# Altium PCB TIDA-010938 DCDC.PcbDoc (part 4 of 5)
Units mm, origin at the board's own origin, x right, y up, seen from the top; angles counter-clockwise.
Board outline 275 x 165 mm, 4 copper layers (Top Layer, Layer 1, Layer 2, Bottom Layer), stack 1.787 mm thick; 436 components, 216 nets, 1367 pads, 1992 vias.
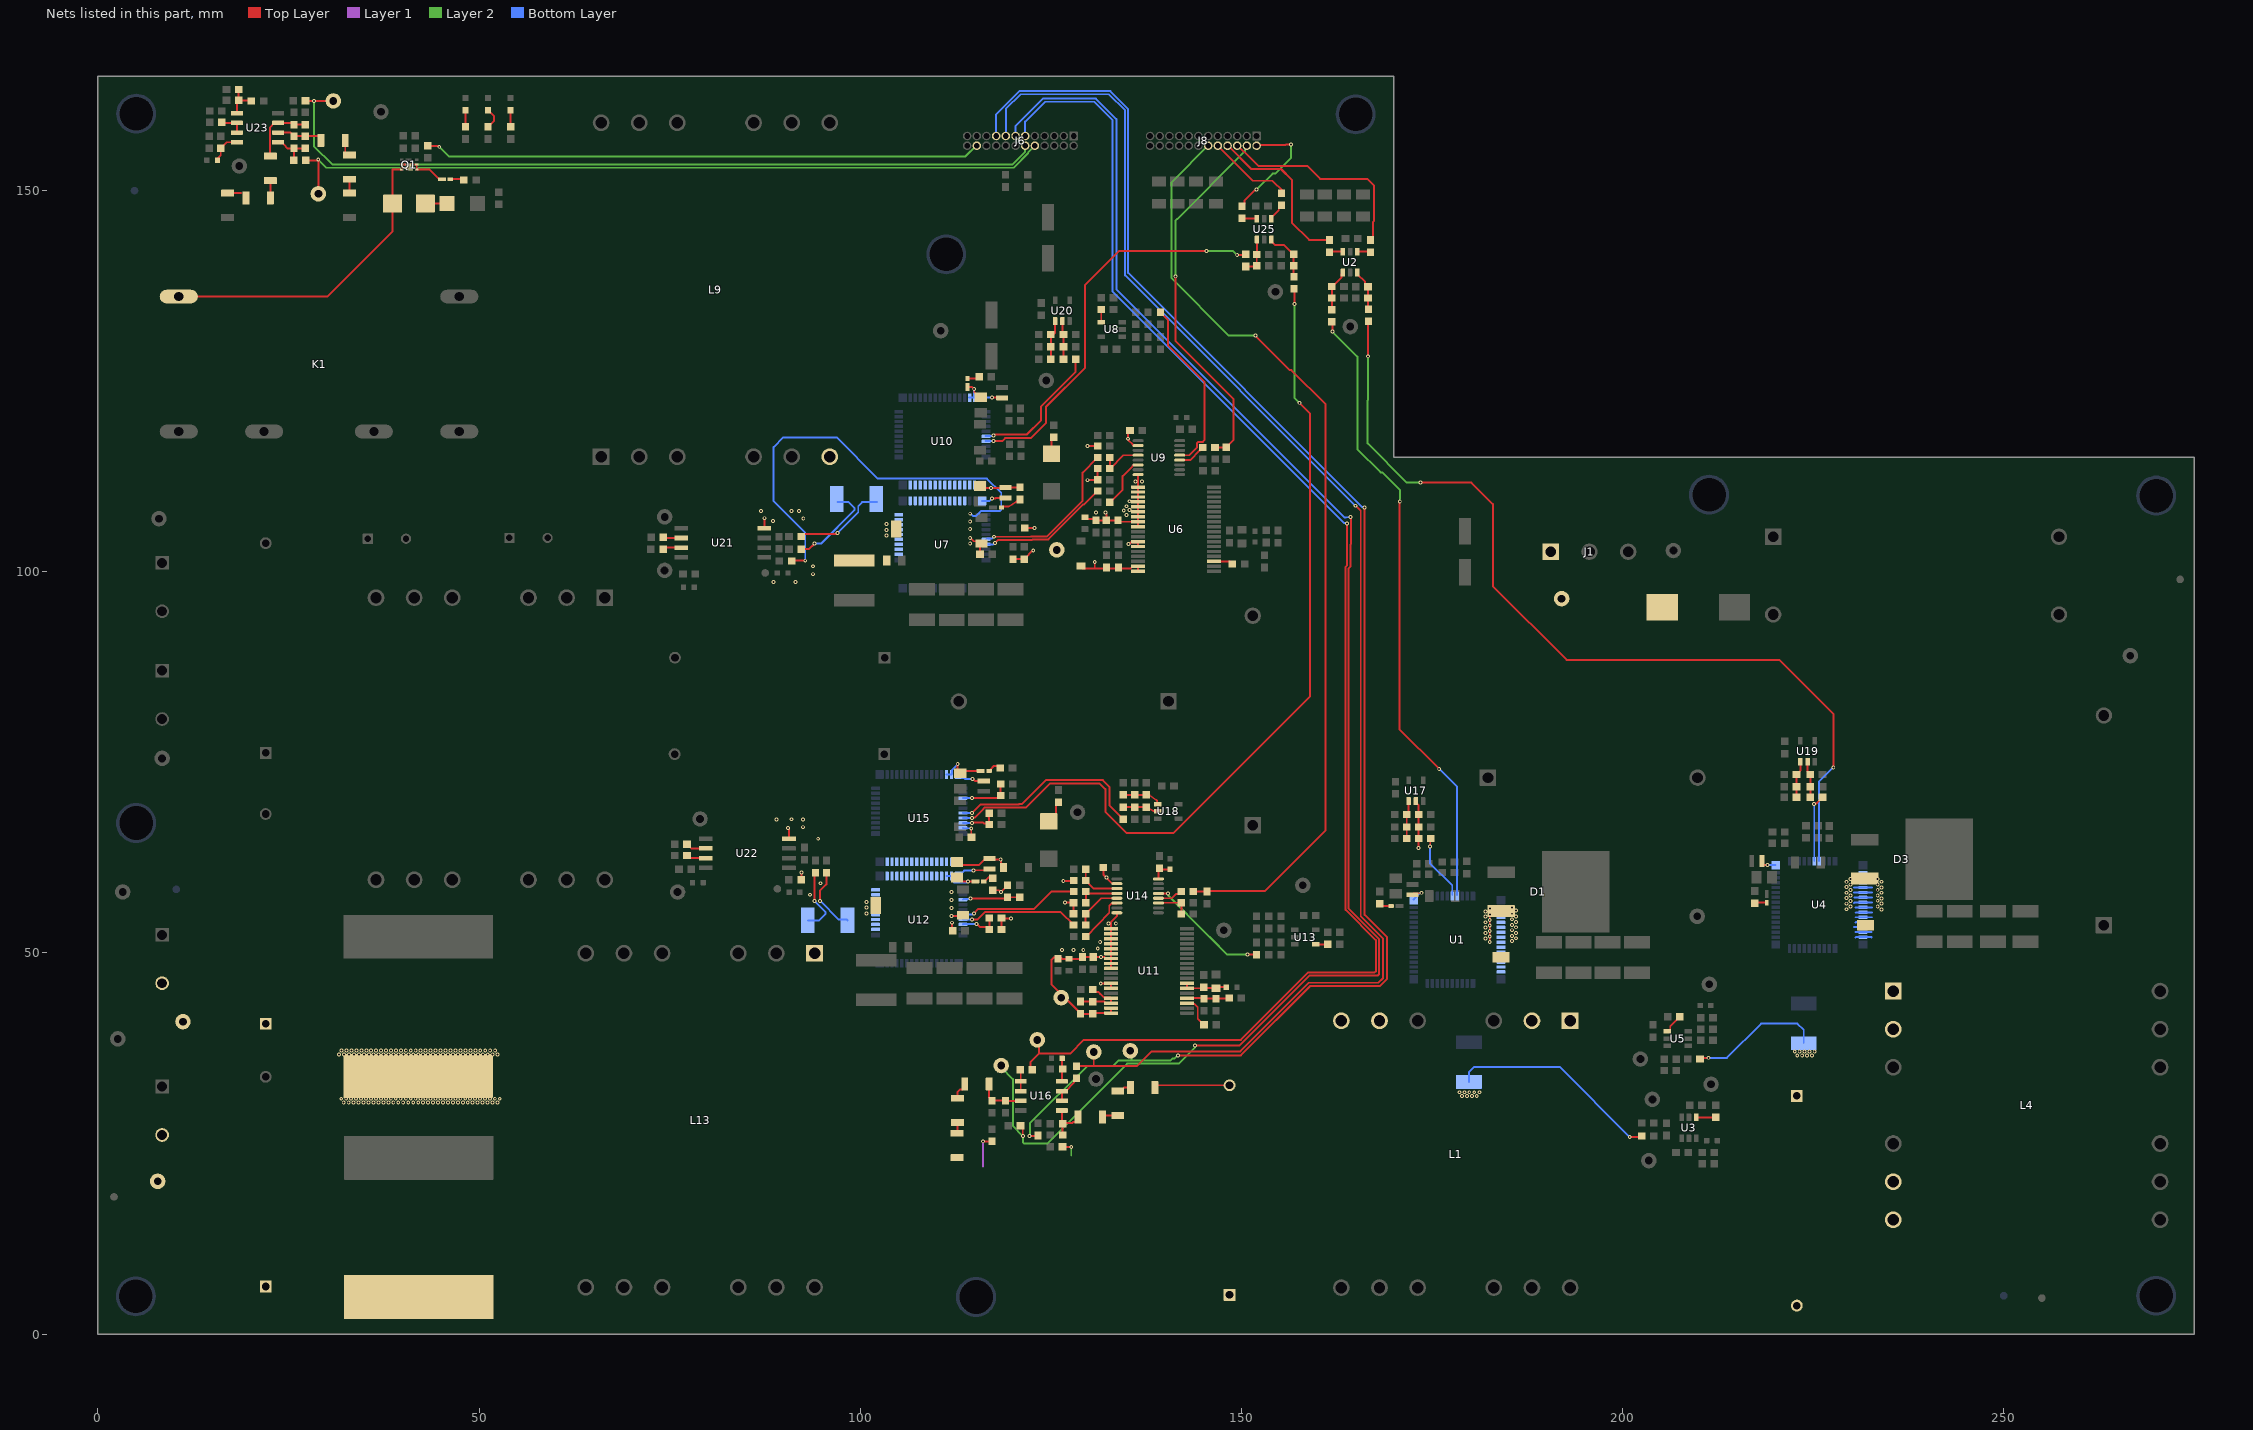
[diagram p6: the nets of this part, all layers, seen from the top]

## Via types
v1: diameter 0.508, hole 0.254, Top Layer to Bottom Layer, tented both sides, 1977 vias
v2: diameter 0.508, hole 0.254, Top Layer to Bottom Layer, 15 vias

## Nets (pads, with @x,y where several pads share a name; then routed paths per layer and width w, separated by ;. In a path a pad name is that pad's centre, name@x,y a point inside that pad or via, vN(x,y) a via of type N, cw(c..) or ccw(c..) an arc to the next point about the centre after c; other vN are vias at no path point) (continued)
NetC65_1: C65.1 D20.1 U10.40 U10.41 | length 4.3
  Top Layer w0.254: D20.1@114.052,124.232 114.678,124.232 114.948,123.962 114.948,123.575 115.632,122.891 C65.1@115.797,122.891
  Bottom Layer w0.254: U10.40@114.274,122.856 114.924,122.856 114.936,122.867 114.936,123.952 v1(114.947,123.964)
NetC66_1: C66.1 R98.1
NetC67_2: C67.2 R75.2 R79.2 U17.1 | length 5
  Top Layer w0.254: R75.2@171.69,65.009 R79.2@171.69,66.509 C67.2@171.69,68.155 171.935,68.4 U17.1@171.935,69.928
NetC69_2: C69.2 R49.2 U12.45 | length 7.2
  Top Layer w0.254: v1(114.462,57.164) 119.185,57.164 C69.2@119.327,57.306 120.556,57.306 R49.2@120.564,57.315
  Bottom Layer w0.254: U12.45@113.462,56.989 113.56,57.087 114.316,57.087 114.394,57.164 v1(114.462,57.164)
NetC73_2: C73.2 C77.1 FB6.2 U11.6 U11.7 | length 6
  Top Layer w0.254: U11.7@142.862,46.02 U11.6@142.862,45.37 144.922,45.37 C77.1@145.062,45.51 145.195,45.377 C73.2@146.672,45.377 146.805,45.51 FB6.2@148.012,45.51
NetC76_1: C76.1 R48.2 R54.1 U11.33 U11.34 | length 7.6
  Top Layer w0.254: R54.1@128.899,43.633 130.474,43.633 C76.1@130.499,43.608 132.023,43.608 132.212,43.42 U11.34@132.912,43.42 U11.33@132.912,44.07 132.814,44.168 131.951,44.168 131.474,44.645 131.22,44.899 130.809,44.899 R48.2@130.512,45.197
NetC78_2: C78.2 R76.2 R80.2 U18.1 | length 5.1
  Top Layer w0.254: R76.2@134.508,70.744 R80.2@136.008,70.744 C78.2@137.508,70.744 137.856,70.701 137.937,70.701 138.85,70.052 138.922,69.98 138.968,69.707 138.968,69.686 U18.1@139.001,69.513
NetC79_2: C79.2 R57.2 U12.50 | length 5.3
  Top Layer w0.254: v1(115.241,53.81) 115.31,53.81 115.687,53.432 116.582,53.432 C79.2@116.93,53.084 R57.2@116.93,54.582
  Bottom Layer w0.254: U12.50@113.462,53.739 113.498,53.774 115.205,53.774 v1(115.241,53.81)
NetC80_1: C80.1 D21.1 U12.40 U12.41 | length 6.1
  Top Layer w0.254: C80.1@112.689,59.897 113.197,59.389 v2@114.11,59.389 ; D21.1@114.964,59.379 v2(114.134,59.379) ; v2@114.11,59.389 114.134,59.412 v2(114.134,59.379) ; v2@114.11,59.389 114.1,59.379 v2(114.134,59.379) ; v2@114.11,59.389 114.124,59.389 v2(114.134,59.379)
  Bottom Layer w0.254: U12.40@111.312,60.099 U12.41@111.962,60.099 112.06,60.001 112.06,59.488 112.302,59.247 113.933,59.247 114.065,59.379 v2(114.134,59.379)
NetC81_2: C81.2 R50.2 R52.2 U11.4 | length 5.6
  Top Layer w0.254: U11.4@142.862,44.07 145.025,44.07 C81.2@145.087,44.007 R52.2@146.672,44.007 148.312,44.007 R50.2@148.387,44.082
NetC82_2: C82.2 R77.2 R81.2 U17.2 | length 6.3
  Top Layer w0.254: U17.2@172.885,69.928 172.885,69.728 173.252,69.361 C82.2@173.252,68.155 R81.2@173.252,66.509 R77.2@173.252,65.009 173.252,63.777 v1@173.241,63.766
  other v1: 173.207,63.766
NetC83_2: C83.2 R78.2 R82.2 U18.2 | length 4.6
  Top Layer w0.254: R78.2@134.508,69.119 R82.2@136.008,69.119 C83.2@137.508,69.119 137.856,68.915 C83.2@137.895,68.915 ; C83.2@137.553,69.119 U18.2@138.583,68.554
NetC84_1: C84.1 FB10.2 U14.16 | length 2.9
  Top Layer w0.254: U14.16@139.116,59.718 139.116,60.995 C84.1@139.246,61.125 139.396,60.975 FB10.2@140.639,60.975
NetC86_2: C86.2 R83.2 R90.2 U19.1 | length 4.9
  Top Layer w0.254: R83.2@222.807,70.424 R90.2@222.807,71.804 C86.2@222.807,73.424 222.832,73.424 223.18,73.772 223.18,73.797 223.312,73.929 U19.1@223.312,75.073
NetC87_2: C87.2 R84.2 R91.2 U20.1 | length 5
  Top Layer w0.254: R84.2@125,127.786 125,129.286 125,130.842 125.025,130.842 125.558,131.375 U20.1@125.558,132.578
NetC88_2: C88.2 R158.1 U14.5 | length 6.4
  Top Layer w0.254: R158.1@129.575,53.673 129.571,53.677 C88.2@129.571,55.147 131.602,57.178 U14.5@133.666,57.178
NetC89_2: C89.2 R59.1 U14.3 | length 6
  Top Layer w0.254: R59.1@129.579,60.99 C89.2@129.579,59.498 130.629,58.448 U14.3@133.666,58.448
NetC90_2: C90.2 R35.1 U9.4 | length 5.9
  Top Layer w0.254: R35.1@132.736,114.981 C90.2@132.736,113.541 132.761,113.541 134.512,115.292 U9.4@136.452,115.292
NetC91_2: C91.2 R85.2 R92.2 U19.2 | length 4.8
  Top Layer w0.254: U19.2@224.262,75.073 224.262,73.772 224.61,73.424 C91.2@224.629,73.424 R92.2@224.629,71.804 R85.2@224.629,70.424
NetC92_2: C92.2 R62.2 U14.11 | length 4.4
  Top Layer w0.254: U14.11@139.116,56.543 139.144,56.571 139.773,56.571 139.788,56.586 C92.2@142.013,56.586 ; R62.2@142.149,55.058 C92.2@142.149,56.525
NetC95_2: C95.2 U15.51 | length 2.3
  Top Layer w0.254: v1(114.556,66.313) 114.556,65.521 114.669,65.408 C95.2@114.669,65.173
  Bottom Layer w0.254: U15.51@113.462,66.406 113.509,66.359 114.509,66.359 v1(114.556,66.313)
NetC96_2: C96.2 R65.2 U15.45 | length 6.6
  Top Layer w0.254: v1(114.669,70.306) 116.412,70.306 116.42,70.313 118.07,70.313 R65.2@118.418,70.661 C96.2@118.418,72.163
  Bottom Layer w0.254: U15.45@113.462,70.306 v1(114.669,70.306)
NetC97_2: C97.2 R89.2 R93.2 U20.2 | length 4.9
  Top Layer w0.254: U20.2@126.508,132.578 126.508,130.992 126.658,130.842 126.658,129.286 R89.2@126.658,127.786
NetC98_2: C98.2 R70.2 U15.50 | length 5.3
  Top Layer w0.254: v1(114.669,67.047) 114.718,67.096 116.095,67.096 116.198,66.993 116.786,66.993 C98.2@116.93,66.849 ; C98.2@116.663,66.533 116.862,66.732 116.862,67.825 R70.2@116.663,68.025
  Bottom Layer w0.254: U15.50@113.462,67.056 113.467,67.051 114.665,67.051 v1(114.669,67.047)
NetC99_1: C99.1 D22.1 U15.40 U15.41 | length 6.5
  Top Layer w0.254: v1(112.781,74.786) 112.781,73.897 C99.1@113.121,73.556 113.45,73.885 D22.1@115.712,73.885
  Bottom Layer w0.254: U15.40@111.312,73.416 U15.41@111.962,73.416 112.06,73.514 112.06,74.026 112.781,74.747 v1(112.781,74.786)
NetC102_2: C102.2 FB3.2 U16.8 | length 3.1
  Top Layer w0.254: U16.8@126.451,33.145 126.451,34.68 C102.2@126.541,34.77 126.475,34.836 FB3.2@126.475,36.175
NetC103_2: C103.2 R42.2 R106.1 U16.5 | length 5.8
  Top Layer w0.254: U16.5@126.451,29.335 126.451,27.69 126.541,27.69 127.79,27.69 127.924,27.824 128.252,27.824 128.575,28.147 R42.2@128.575,28.475 ; R106.1@126.541,26.125 C103.2@126.541,27.6
NetC104_2: C104.2 R53.2 R139.1 U23.3 | length 9.1
  Top Layer w0.254: R53.2@21.966,154.608 22.253,154.608 22.576,154.931 22.576,158.308 23.153,158.885 U23.3@23.628,158.885 25.481,158.885 C104.2@25.708,158.658 R139.1@27.206,158.658
NetC105_2: C105.2 R31.2 R140.2 U16.3 | length 6.1
  Top Layer w0.254: R31.2@116.91,32.805 116.91,31.029 117.294,30.645 R140.2@117.294,30.62 C105.2@119.052,30.62 119.067,30.605 U16.3@121.051,30.605
NetC109_1: C109.1 R74.2 R141.1 U23.2 | length 6.2
  Top Layer w0.254: U23.2@23.628,157.615 25.263,157.615 25.708,157.17 C109.1@25.708,157.145 R141.1@27.206,157.145 28.918,157.145 29.241,156.822 R74.2@29.241,156.582
NetC109_2: C109.2 R141.2 R152.1 U23.1 | length 5.5
  Top Layer w0.254: U23.1@23.628,156.345 24.103,156.345 24.635,155.813 24.635,155.762 24.852,155.545 C109.2@25.708,155.545 ; R152.1@25.681,153.977 25.708,154.004 C109.2@25.708,155.545 ; R141.2@27.206,155.545 C109.2@25.708,155.545
NetC116_2: C116.2 R109.2 R131.2 U2.1 | length 5.5
  Top Layer w0.254: R109.2@161.859,134.38 R131.2@161.859,135.914 C116.2@161.859,137.417 161.884,137.417 163.128,138.661 163.128,139.085 U2.1@163.301,139.258
NetC118_2: C118.2 R112.2 R129.2 U2.3 | length 5.4
  Top Layer w0.254: U2.3@165.201,139.258 165.201,139.058 166.236,138.023 166.236,137.731 166.584,137.383 C118.2@166.601,137.383 R129.2@166.601,135.919 166.601,134.512 R112.2@166.665,134.448
NetC120_2: C120.2 R117.2 R127.2 U25.1 | length 4.9
  Top Layer w0.254: R117.2@150.557,140.05 151.898,140.05 R127.2@152.005,140.158 C120.2@152.005,141.619 152.042,141.656 U25.1@152.042,143.538
NetC122_2: C122.2 R120.2 R125.2 U25.3 | length 6.8
  Top Layer w0.254: U25.3@153.93,143.586 153.93,143.386 154.455,142.861 155.608,142.861 156.819,141.65 C122.2@156.844,141.65 R125.2@156.844,140.158 156.844,138.785 R120.2@156.908,138.722
NetC151_2: C151.2 R60.1 U14.4 | length 5.6
  Top Layer w0.254: C151.2@129.571,56.6 129.582,56.612 R60.1@129.582,58.054 129.823,57.813 U14.4@133.666,57.813
NetC153_2: C153.2 R12.2 R41.1 U23.5 | length 4.9
  Top Layer w0.254: U23.5@18.228,160.155 18.228,161.62 R41.1@18.458,161.85 ; R12.2@18.458,163.25 R41.1@18.458,161.85 ; C153.2@20.128,161.775 20.053,161.85 R41.1@18.458,161.85
NetC155_2: C155.2 FB11.2 U23.8 | length 3.9
  Top Layer w0.254: FB11.2@15.686,154.25 16.108,154.672 C155.2@16.108,155.545 16.108,155.57 16.883,156.345 U23.8@18.228,156.345
NetD1_2: D1.2 L1.1 L1.2 TP12.1 U1.2 U1.3 U1.4 U1.5 U1.6 U1.7 U1.8 U1.9 U1.10 U1.11 U1.12 U1.13 U1.14 U1.15 | length 4.4
  Top Layer w0.254: v1(182.577,51.461) 182.577,55.061 182.6,55.083 v1(182.6,55.821)
  other v1: 185.487,51.547 182.035,51.902 186.009,51.93 182.577,52.154 185.487,52.239 182.035,52.595 186.009,52.623 182.577,52.898 185.487,52.984 182.035,53.34 186.009,53.367 182.577,53.591 185.487,53.676 182.035,54.032 186.009,54.06 182.577,54.335 185.487,54.421 182.035,54.777 186.009,54.805 182.6,55.061 185.495,55.145 182.035,55.425 186.009,55.574 185.495,55.99
NetD3_2: D3.2 L4.1 L4.2 TP16.1 U4.2 U4.3 U4.4 U4.5 U4.6 U4.7 U4.8 U4.9 U4.10 U4.11 U4.12 U4.13 U4.14 U4.15 | length 24.5
  Bottom Layer w0.254: 230.375,53.385 U4.13@231.532,53.385 232.603,53.385 ; 230.375,56.573 230.438,56.635 U4.8@231.532,56.635 232.739,56.635 232.744,56.64 ; 230.375,57.935 U4.6@231.532,57.935 232.744,57.935 ; 230.375,58.585 U4.5@231.532,58.585 232.744,58.585 ; 230.438,57.284 230.439,57.285 U4.7@231.532,57.285 232.719,57.285 232.744,57.311 ; 230.562,52.049 230.598,52.085 U4.15@231.532,52.085 232.628,52.085 232.665,52.049 ; 230.562,52.735 U4.14@231.532,52.735 232.665,52.735 ; 230.562,53.973 230.624,54.035 U4.12@231.532,54.035 232.599,54.035 232.665,54.101 ; 230.562,54.685 U4.11@231.532,54.685 232.719,54.685 ; 230.562,55.273 230.624,55.335 U4.10@231.532,55.335 232.692,55.335 ; 230.562,55.985 U4.9@231.532,55.985 232.692,55.985
  other v1: 233.972,55.721 229.382,55.735 229.901,56.078 233.462,56.106 229.382,56.46 233.972,56.465 229.901,56.822 233.462,56.85 233.972,57.158 229.382,57.204 229.901,57.515 233.462,57.543 229.382,57.897 233.972,57.902 229.901,58.26 233.462,58.287 233.972,58.595 229.382,58.641 229.901,58.952 233.462,58.98 229.382,59.334 233.972,59.339 229.901,59.697 233.462,59.724
NetD5_2: D5.2 R21.2 | length 3.6
  Top Layer w0.254: D5.2@124.148,116.402 D5.2@125.075,115.475 125.075,117.342 R21.2@125.37,117.637
NetD8_2: D8.2 R46.2 | length 3.1
  Top Layer w0.254: D8.2@123.731,67.004 D8.2@123.781,67.004 ; D8.2@124.721,67.261 125.661,68.2 125.661,69.431 R46.2@126.009,69.779
NetD11_2: D11.2 D12.2 | length 2.8
  Top Layer w0.254: D11.2@42.944,148.312 D12.2@45.794,148.312
NetD13_1: D13.1 R147.2 | length 2
  Top Layer w0.254: R147.2@48.211,158.424 D13.1@48.211,160.406
NetD14_2: D14.2 R7.2 | length 1.7
  Top Layer w0.254: D14.2@46.375,151.5 47.916,151.5 R7.2@48.007,151.41
NetD15_1: D15.1 R153.2 | length 2.8
  Top Layer w0.254: R153.2@51.177,158.375 51.977,159.175 51.977,159.742 D15.1@51.177,160.542
NetD16_1: D16.1 R154.2 | length 2.1
  Top Layer w0.254: R154.2@54.142,158.432 D16.1@54.142,160.542
NetD17_2: D17.2 R105.2 | length 1.6
  Top Layer w0.254: R105.2@168.131,56.456 168.428,56.159 D17.2@169.631,56.159
NetD18_2: D18.2 R132.2 | length 1.6
  Top Layer w0.254: R132.2@217.328,56.52 217.448,56.64 D18.2@218.902,56.64
NetD19_2: D19.2 R133.2 | length 2.8
  Top Layer w0.254: D19.2@118.524,108.426 118.647,108.549 119.454,108.549 ; 119.455,108.55 120.587,109.26 120.605,109.26 R133.2@120.953,109.49
NetD20_2: D20.2 R135.2 | length 1.6
  Top Layer w0.254: D20.2@114.052,125.347 115.345,125.347 R135.2@115.595,125.597
NetD21_2: D21.2 R136.2 | length 1.4
  Top Layer w0.254: D21.2@116.204,59.379 116.304,59.379 116.893,59.968 117.297,59.968 R136.2@117.297,59.898
NetD22_2: D22.2 R138.2 | length 1.9
  Top Layer w0.254: D22.2@116.899,73.885 116.999,73.885 117.122,74.008 117.122,74.108 117.541,74.526 118.097,74.526 R138.2@118.369,74.255
NetJ1_1: J1.1 L3.2 TP40.1
NetL2_2: L2.2 U1.42 | length 2.7
  Top Layer w0.254: L2.2@172.425,57.634 172.623,57.832 173.497,57.832 173.556,57.892 v1(173.625,57.892)
  Bottom Layer w0.254: U1.42@172.591,57.042 172.616,57.042 173.417,57.843 173.576,57.843 v1(173.625,57.892)
NetL5_2: L5.2 U4.42 | length 2.2
  Top Layer w0.254: L5.2@218.291,62.067 218.291,61.734 218.489,61.536 v1(219.026,61.536)
  Bottom Layer w0.254: v1@219.026,61.51 U4.42@220.082,61.51
NetL7_2: L7.2 U7.42 | length 3.3
  Top Layer w0.254: v2(117.262,109.611) 117.706,109.611 117.803,109.708 L7.2@119.048,109.708
  Bottom Layer w0.254: U7.42@115.983,109.304 116.987,109.304 117.262,109.58 v2(117.262,109.611)
NetL9_6: L9.6 R58.1 R134.1 | length 12
  Top Layer w0.254: R58.1@92.249,102.944 92.273,102.967 93.255,102.967 v1(94,103.712)
  Bottom Layer w0.254: v1(94,103.712) 94.863,103.712 99.231,108.081 99.231,108.376 98.474,109.133 R134.1@96.989,109.133
NetL10_2: L10.2 U10.42 | length 2.7
  Top Layer w0.254: v1(117.259,122.867) 117.28,122.846 118.59,122.846 L10.2@118.611,122.826
  Bottom Layer w0.254: U10.42@115.899,122.856 117.247,122.856 v1(117.259,122.867)
NetL11_2: L11.2 U12.42 | length 4.4
  Top Layer w0.254: v2(114.843,60.798) 114.892,60.846 116.774,60.846 L11.2@116.968,61.04
  Bottom Layer w0.254: U12.42@112.937,60.099 112.937,60.124 113.611,60.798 v2(114.843,60.798)
NetL13_1: L13.1 R96.1 R137.1 | length 8.5
  Top Layer w0.254: v1(94,56.813) R96.1@94,60.403
  Bottom Layer w0.254: R137.1@93.125,54.286 94.599,54.286 95.457,55.145 95.457,55.356 v1(94,56.813)
NetL14_2: L14.2 U15.42 | length 3.6
  Top Layer w0.254: v1(114.734,72.822) 114.761,72.822 115.017,72.565 L14.2@116.198,72.565
  Bottom Layer w0.254: U15.42@112.937,73.416 112.937,73.391 113.36,72.968 113.575,72.968 113.721,72.822 v1(114.734,72.822)
NetR4_1: R4.1 U8.4 | length 1.7
  Top Layer w0.254: R4.1@131.611,134.417 131.614,134.413 U8.4@131.614,132.735
NetR8_1: R8.1 U3.1 | length 2.6
  Top Layer w0.254: U3.1@209.657,28.434 212.2,28.434 R8.1@212.207,28.44
NetR14_1: R14.1 U13.4 | length 1.6
  Top Layer w0.254: U13.4@159.73,51.128 R14.1@161.328,51.128
NetR19_1: R19.1 U5.1 | length 2.7
  Top Layer w0.254: U5.1@205.881,39.716 206.081,39.716 206.254,39.889 206.254,40.376 207.127,41.25 207.127,41.275 207.475,41.623 R19.1@207.5,41.623
NetR22_2: R22.2 U6.3 | length 2.6
  Top Layer w0.254: U6.3@146.395,101.367 147.815,101.367 147.821,101.361 148.468,101.361 R22.2@148.816,101.013
NetR26_1: R26.1 U23.6 U23.7 | length 3.3
  Top Layer w0.254: R26.1@16.261,158.983 16.36,158.885 U23.6@18.228,158.885 U23.7@18.228,157.615
NetR28_2: R28.2 R30.1 | length 1.4
  Top Layer w0.254: R28.2@112.693,26.348 112.729,26.384 112.729,27.714 R30.1@112.766,27.75
NetR30_2: R30.2 R31.1 | length 2.4
  Top Layer w0.254: R30.2@112.766,30.95 112.766,31.781 113.067,32.082 113.387,32.082 113.71,32.405 R31.1@113.71,32.805
NetR33_2: R33.2 R36.1 | length 1.9
  Top Layer w0.254: R36.1@133.775,31.895 134.175,31.895 134.621,32.341 R33.2@135.447,32.341
NetR36_2: R36.2 R42.1 | length 2.1
  Top Layer w0.254: R42.1@131.775,28.475 131.995,28.695 R36.2@133.775,28.695
NetR38_1: R38.1 U9.6 | length 6.8
  Top Layer w0.254: R38.1@132.736,109.118 132.761,109.118 134.419,110.776 134.419,112.554 135.73,113.864 135.888,114.022 U9.6@136.452,114.022
NetR43_2: R43.2 R44.1 | length 1.8
  Top Layer w0.254: R43.2@17.011,149.675 18.778,149.675
NetR44_2: R44.2 R53.1 | length 1.9
  Top Layer w0.254: R53.1@22.469,151.472 R53.1@22.617,151.323 22.629,151.311 R44.2@22.629,149.589
NetR47_2: R47.2 U11.3 | length 4.3
  Top Layer w0.254: U11.3@142.862,43.42 142.96,43.322 143.822,43.322 144.268,42.876 144.268,41.363 145.062,40.569 R47.2@145.087,40.569
NetR51_2: R51.2 U9.12 | length 3.7
  Top Layer w0.254: U9.12@141.902,114.657 143.296,114.657 144.561,115.923 144.561,115.948 144.909,116.296 R51.2@144.934,116.296
NetR61_2: R61.2 U21.6 | length 2.4
  Top Layer w0.254: R61.2@74.139,104.52 74.225,104.434 U21.6@76.52,104.434
NetR63_1: R63.1 U14.6 | length 6.4
  Top Layer w0.254: R63.1@129.667,52.144 132.664,55.282 132.664,56.172 133.007,56.515 133.638,56.515 U14.6@133.666,56.543
NetR66_2: R66.2 U21.7 | length 2.5
  Top Layer w0.254: R66.2@74.139,102.964 74.339,103.164 U21.7@76.52,103.164
NetR68_2: R68.2 R69.1 | length 1.8
  Top Layer w0.254: R68.2@33,149.675 R69.1@33,151.491
NetR69_2: R69.2 R74.1 | length 2.3
  Top Layer w0.254: R74.1@32.441,156.582 32.441,155.014 32.764,154.691 R69.2@33,154.691
NetR73_2: R73.2 U22.6 | length 2.7
  Top Layer w0.254: R73.2@77.267,64.27 77.292,64.27 77.64,63.922 77.64,63.897 77.827,63.71 U22.6@79.739,63.71
NetR86_1: R86.1 U16.1 U16.2 | length 2.9
  Top Layer w0.254: R86.1@120.961,34.695 121.051,34.605 U16.1@121.051,33.145 U16.2@121.051,31.875
NetR87_1: R87.1 U16.6 U16.7 | length 4
  Top Layer w0.254: U16.6@126.451,30.605 U16.7@126.451,31.875 126.926,31.875 128.023,32.972 128.023,33.207 R87.1@128.371,33.555
NetR95_2: R95.2 U22.7 | length 2.6
  Top Layer w0.254: R95.2@77.267,62.8 77.615,62.452 77.777,62.452 77.789,62.44 U22.7@79.739,62.44
NetR108_1: R108.1 U2.6 | length 1.8
  Top Layer w0.254: R108.1@161.56,141.933 161.635,142.008 U2.6@163.301,142.008
NetR113_1: R113.1 U2.4 | length 1.8
  Top Layer w0.254: U2.4@165.201,142.008 166.845,142.008 R113.1@166.92,141.933
NetR116_1: R116.1 U25.6 | length 2
  Top Layer w0.254: R116.1@150.082,146.369 150.115,146.336 U25.6@152.03,146.336
NetR121_1: R121.1 U25.4 | length 2
  Top Layer w0.254: U25.4@154.03,146.569 154.03,146.636 154.103,146.709 154.17,146.709 154.896,147.436 154.896,147.696 155.078,147.878 R121.1@155.338,147.878
NetR159_2: R159.2 U14.12 | length 3.3
  Top Layer w0.254: U14.12@139.116,57.178 140.87,57.178 141.414,57.722 141.715,57.722 142.013,58.02 R159.2@142.013,58.054
O\C\__Bat_H1_Buff: R5.1 U9.13 | length 23.6
  Top Layer w0.254: R5.1@139.37,134.061 139.37,134.036 140.343,133.064 140.343,129.695 145.183,124.855 145.183,117.294 144.936,117.048 144.319,117.048 144.157,116.885 144.157,116.564 144.157,116.269 143.181,115.292 U9.13@141.902,115.292
O\C\_Bat_H1_init: R35.2 U7.48 | length 21.3
  Top Layer w0.254: v1(117.556,104.6) 119.206,104.6 119.211,104.596 122.375,104.596 122.427,104.648 124.499,104.648 129.154,109.303 129.154,113.025 131.111,114.981 R35.2@131.136,114.981
  Bottom Layer w0.254: U7.48@116.508,104.244 116.606,104.342 117.229,104.342 117.487,104.6 v1(117.556,104.6)
O\C\_Bat_H2_Buff: R15.1 U14.13 | length 16.4
  Top Layer w0.254: U14.13@139.116,57.813 v1(140.387,57.813) ; v1(150.789,49.778) R15.1@151.97,49.778
  Layer 2 w0.254: v1(140.387,57.813) 140.436,57.764 140.436,57.471 145.394,52.513 146.076,51.831 148.129,49.778 v1(150.789,49.778)
O\C\_Bat_H2_init: R60.2 U12.48 | length 15.8
  Top Layer w0.254: v1(114.92,55.169) 114.92,55.238 115.438,55.755 122.767,55.755 125.065,58.054 R60.2@127.982,58.054
  Bottom Layer w0.254: U12.48@113.462,55.039 113.477,55.053 114.736,55.053 114.852,55.169 v1(114.92,55.169)
O\C\_Bat_L1_init: R89.1 U10.48 | length 18.1
  Top Layer w0.254: v1(117.457,117.866) 117.526,117.866 117.68,118.021 121.87,118.021 123.725,119.876 123.725,121.708 128.258,126.241 R89.1@128.258,127.888
  Bottom Layer w0.254: U10.48@116.424,117.796 116.46,117.831 117.422,117.831 v1(117.457,117.866)
O\C\_Bat_L2_init: R78.1 U15.48 | length 26.5
  Top Layer w0.254: v1(114.669,68.365) 115.801,69.498 120.793,69.498 120.809,69.513 121.193,69.513 124.353,72.673 131.814,72.673 132.691,71.795 132.691,69.36 134.508,67.544 R78.1@134.508,67.519 R78.1@134.508,67.444
  Bottom Layer w0.254: U15.48@113.462,68.356 113.467,68.36 114.664,68.36 v1(114.669,68.365)
O\C\_Boost1_init: R77.1 U1.48 | length 8.7
  Top Layer w0.254: v1@174.768,63.942 174.768,64.925 R77.1@174.852,65.009
  Bottom Layer w0.254: v1(174.733,63.942) 174.733,61.787 177.651,58.87 U1.48@177.651,57.567
O\C\_Boost2_init: R85.1 U4.48 | length 9
  Top Layer w0.254: v1(225.108,69.545) 225.157,69.593 225.374,69.593 226.204,70.424 R85.1@226.229,70.424
  Bottom Layer w0.254: v1(225.108,69.545) 225.142,69.511 U4.48@225.142,62.035
"PV1 Bus+": C9.2 L1.5 L1.6 L6.2 R33.1 | length 9.9
  Top Layer w0.254: R33.1@138.647,32.341 138.949,32.644 C9.2@148.439,32.644
  other v1: 32.893,30.371 33.543,30.371 34.193,30.371 34.843,30.371 35.493,30.371 36.143,30.371 36.793,30.371 37.443,30.371 38.093,30.371 38.743,30.371 39.393,30.371 40.043,30.371 41.363,30.371 42.013,30.371 42.663,30.371 43.313,30.371 43.963,30.371 44.613,30.371 45.263,30.371 45.913,30.371 46.563,30.371 47.213,30.371 47.863,30.371 48.513,30.371 49.788,30.371 50.438,30.371 51.088,30.371 51.738,30.371 52.388,30.371 32.236,30.381 40.706,30.381 49.131,30.381 31.913,30.879 32.563,30.879 33.213,30.879 33.863,30.879 34.513,30.879 35.163,30.879 35.813,30.879 36.463,30.879 37.113,30.879 37.763,30.879 38.413,30.879 39.063,30.879 39.713,30.879 40.383,30.879 41.033,30.879 41.683,30.879 42.333,30.879 42.983,30.879 43.633,30.879 44.283,30.879 44.933,30.879 45.583,30.879 46.233,30.879 46.883,30.879 47.533,30.879 48.183,30.879 48.808,30.879 49.458,30.879 50.108,30.879 50.758,30.879 51.408,30.879 52.058,30.879 52.708,30.879 31.638,36.7 32.288,36.7 32.938,36.7 33.588,36.7 34.238,36.7 34.888,36.7 35.538,36.7 36.163,36.7 36.813,36.7 37.463,36.7 38.113,36.7 38.763,36.7 39.413,36.7 40.063,36.7 40.713,36.7 41.363,36.7 42.013,36.7 42.663,36.7 43.313,36.7 43.963,36.7 44.633,36.7 45.283,36.7 45.933,36.7 46.583,36.7 47.233,36.7 47.883,36.7 48.533,36.7 49.183,36.7 49.833,36.7 50.483,36.7 51.133,36.7 51.783,36.7 52.433,36.7 31.958,37.208 32.608,37.208 33.258,37.208 33.908,37.208 34.558,37.208 35.215,37.197 35.833,37.208 36.483,37.208 37.133,37.208 37.783,37.208 38.433,37.208 39.083,37.208 39.733,37.208 40.383,37.208 41.033,37.208 41.683,37.208 42.333,37.208 42.983,37.208 43.64,37.197 44.303,37.208 44.953,37.208 45.603,37.208 46.253,37.208 46.903,37.208 47.553,37.208 48.203,37.208 48.853,37.208 49.503,37.208 50.153,37.208 50.803,37.208 51.453,37.208 52.11,37.197
"PV1 Bus-": C9.1 C30.1 J2.2 R10.1 R17.1 R107.1 TP41.1 | length 30.4
  Top Layer w0.254: R107.1@126.53,24.571 v1(127.678,24.571) ; v1(200.938,25.854) 202.376,25.854 R10.1@202.504,25.982
  Layer 2 w0.254: 127.678,23.435 v1(127.678,24.571)
  Bottom Layer w0.254: R17.1@179.842,33.083 179.842,34.368 180.542,35.068 191.725,35.068 v1(200.938,25.854)
  other v1: 178.922,31.218 179.572,31.218 180.222,31.218 180.872,31.218 178.592,31.726 179.242,31.726 179.892,31.726 180.542,31.726 181.21,31.726
"PV2 Bus+": C23.2 L4.5 L4.6 L8.2 R28.1
"PV2 Bus-": C23.1 C224.1 J3.2 R18.1 R71.1 R111.1 TP44.1 | length 22.2
  Top Layer w0.254: v1@116.06,25.326 v1(116.092,25.294) R111.1@117.279,25.294 ; R71.1@210.156,36.083 210.321,36.249 v1(211.265,36.249)
  Layer 1 w0.254: 116.092,22 v1(116.092,25.294)
  Bottom Layer w0.254: v1@211.265,36.229 213.667,36.229 218.182,40.744 222.922,40.744 223.767,39.899 R18.1@223.767,38.163
  other v1: 222.912,36.544 223.562,36.544 224.212,36.544 224.862,36.544 222.582,37.052 223.232,37.052 223.882,37.052 224.532,37.052 225.199,37.052
RY_DCPreCharge: J6.22 R144.1 | length 73.1
  Top Layer w0.254: R144.1@43.266,155.891 43.291,155.866 44.59,155.866 44.706,155.75 v1(44.775,155.75)
  Layer 2 w0.254: v1(44.775,155.75) 46.025,154.5 113.803,154.5 J6.22@115.199,155.896
SN_DCPreCharge: D11.1 D14.1 K1.1 Q1.1 Q1.2 Q1.5 Q1.6 Q1.8 | length 47.9
  Top Layer w0.254: K1.1@10.6,136.1 30.1,136.1 38.644,144.644 D11.1@38.644,148.312 38.644,152.766 Q1.6@39.869,152.766 Q1.5@39.869,153.416 39.883,153.401 40.533,153.401 Q1.8@40.844,153.091 41.154,153.401 41.804,153.401 Q1.2@41.819,153.416 Q1.1@41.819,152.766 43.509,152.766 D14.1@44.775,151.5
SW1: C34.2 C35.1 C36.1 C37.1 C38.1 C40.1 C41.2 C42.2 C45.1 C46.2 C48.2 C51.2 C54.1 C55.1 C90.1 D6.2 L7.1 R29.2 R32.1 R56.1 R133.1 R134.2 TP3.1 TP9.1 U6.19 U6.20 U6.21 U6.22 U6.23 U6.24 U6.25 U6.26 U6.27 U6.30 U6.31 U6.35 U6.36 U7.18 U7.19 U7.20 U7.21 U7.22 U7.23 U7.24 U7.25 U7.26 U7.28 U7.29 U7.30 U7.31 U7.32 U7.33 U7.34 U7.35 U7.36 U7.37 U7.38 U7.39 U9.2 U9.8 U10.2 U10.3 U10.4 U10.5 U10.6 U10.7 U10.8 U10.9 U10.10 U10.11 U10.12 U10.13 U10.14 U10.15 U21.4 | length 118.4
  Top Layer w0.254: U21.4@87.42,105.704 v1(87.42,107.03) ; C48.2@90.987,101.407 91.037,101.456 v1(92.78,101.456) ; R56.1@92.249,104.634 92.597,104.982 96.817,104.982 96.92,105.085 v1(96.989,105.085) ; v2(114.42,104.456) 114.869,104.007 115.623,104.007 C34.2@115.917,103.712 115.708,103.503 C36.1@115.708,102.294 ; C46.2@115.71,111.249 116.383,111.008 cw(c116.383,110.754) 116.386,111.008 v2(117.154,110.999) 117.921,110.99 117.932,110.99 118.367,110.985 118.375,110.985 119.05,111.033 119.277,111.048 119.721,111.06 119.736,111.06 120.602,111.081 120.605,111.081 R133.1@120.953,111.09 ; C45.1@120.031,101.665 R32.1@121.523,101.665 ; R32.1@121.55,101.718 122.65,102.817 v1(122.693,102.817) ; C35.1@121.593,105.752 v1(122.851,105.752) ; D6.2@129.143,100.411 130.709,100.411 ; C41.2@129.346,106.942 130.691,106.942 130.923,106.71 130.962,106.749 C40.1@132.264,106.749 ; v1(129.827,112.017) 131.062,112.017 C54.1@131.136,112.09 C90.1@131.136,113.541 ; v1(129.827,116.507) 131.126,116.507 C55.1@131.136,116.516 ; v1(130.762,101.275) 130.762,100.464 130.709,100.411 ; v1(132.178,107.778) 132.178,107.709 132.276,107.611 132.276,106.761 C40.1@132.264,106.749 ; v1(135.119,117.454) 135.167,117.405 135.167,117.283 135.73,116.72 135.888,116.562 U9.2@136.452,116.562 ; v1(135.185,103.629) 135.254,103.629 135.494,103.869 136.347,103.869 U6.30@136.445,103.967 U6.31@136.445,103.317 ; v1@135.218,117.422 135.119,117.522 135.119,118.262 C51.2@135.377,118.521 ; U6.36@136.445,100.067 U6.35@136.445,100.717 135.745,100.717 135.44,100.411 130.709,100.411 ; U6.27@136.445,105.917 U6.26@136.445,106.567 ; U9.8@136.452,112.752 136.452,111.124 U6.19@136.445,111.117 U6.20@136.445,110.467 U6.21@136.445,109.817 U6.22@136.445,109.167 U6.23@136.445,108.517 U6.24@136.445,107.867 U6.25@136.445,107.217 U6.26@136.445,106.567 ; C40.1@132.264,106.749 C37.1@133.801,106.749 133.983,106.567 U6.26@136.445,106.567
  Bottom Layer w0.254: v1(92.78,101.456) 92.78,105.124 88.643,109.262 88.643,116.344 89.925,117.626 96.91,117.626 102.308,112.227 116.619,112.227 118.497,110.349 118.497,108.145 118.348,107.996 115.847,107.996 115.656,107.805 115.656,107.778 115.216,107.338 114.772,107.338 114.489,107.621 v2(114.42,107.621) ; v1(96.989,105.085) 99.739,107.835 99.739,108.625 100.246,109.133 R134.2@102.189,109.133
  other v1: 88.612,98.676 91.522,98.676 93.783,99.683 93.783,100.725 103.442,104.754 103.442,105.504 103.442,106.254 114.42,106.581 88.565,106.649 92.524,106.986 134.916,107.458 130.907,107.803 87,107.99 91,107.996 91.984,107.996 134.564,108.051 135.331,108.117 134.916,108.595 135.331,109.254 136.106,111.848 136.952,111.863
  other v2: 114.42,103.716 114.42,105.601
SW2: C56.2 C68.2 C69.1 C70.1 C71.1 C72.1 C74.1 C75.2 C76.2 C79.1 C80.2 C85.2 C88.1 C89.1 C151.1 D9.2 L11.1 R54.2 R57.1 R67.1 R136.1 R137.2 TP6.1 TP10.1 U11.19 U11.20 U11.21 U11.22 U11.23 U11.24 U11.25 U11.26 U11.27 U11.30 U11.31 U11.35 U11.36 U12.18 U12.19 U12.20 U12.21 U12.22 U12.23 U12.24 U12.25 U12.26 U12.28 U12.29 U12.30 U12.31 U12.32 U12.33 U12.34 U12.35 U12.36 U12.37 U12.38 U12.39 U14.2 U14.8 U15.2 U15.3 U15.4 U15.5 U15.6 U15.7 U15.8 U15.9 U15.10 U15.11 U15.12 U15.13 U15.14 U15.15 U22.4 | length 64.8
  Top Layer w0.254: v1(90.531,66.406) 90.531,66.337 90.639,66.229 U22.4@90.639,64.98 ; C56.2@92.239,59.611 92.278,59.65 v1(92.278,60.551) ; v1(94.733,56.832) 94.714,56.85 94.714,58.166 95.553,59.004 R67.1@95.553,60.522 ; v2(112.009,53.968) 112.009,53.042 C70.1@112.137,52.913 ; v2@112.024,54.834 113.373,54.834 C68.2@113.462,54.924 ; C80.2@112.689,61.929 113.055,61.563 115.594,61.563 L11.1@116.648,62.616 ; L11.1@116.566,62.39 L11.1@116.968,62.39 ; L11.1@116.71,62.511 L11.1@116.784,62.511 ; L11.1@117.184,62.175 117.289,62.279 v1(118.423,62.279) 118.423,62.21 118.487,62.146 118.487,61.53 D9.2@118.817,61.2 ; L11.1@117.278,62.191 L11.1@117.336,62.249 ; R136.1@117.369,58.223 118.193,58.223 118.398,58.018 v1(118.459,58.018) 118.463,58.018 119.327,58.881 C69.1@119.327,58.906 ; C79.1@118.53,53.084 R57.1@118.53,54.582 118.583,54.53 v1(119.76,54.53) ; v1(126.633,59.422) 127.904,59.422 C89.1@127.979,59.498 ; v1(126.849,56.6) C151.1@127.971,56.6 C88.1@127.971,55.147 ; v1(131.549,45.991) 131.563,46.005 132.897,46.005 U11.30@132.912,46.02 U11.31@132.912,45.37 ; C85.2@131.891,61.2 131.891,60.293 133.074,59.111 133.638,59.111 U14.2@133.666,59.083 ; U11.35@132.912,42.77 U11.36@132.912,42.12 130.611,42.12 C76.2@130.499,42.008 128.924,42.008 R54.2@128.899,42.033 128.899,42.058 125.065,45.892 125.065,49.077 125.368,49.379 126.335,49.379 126.478,49.236 128.905,49.236 C71.1@129.147,49.478 C74.1@130.548,49.478 v1(131.602,49.478) 132.003,49.478 132.212,49.27 U11.25@132.912,49.27 ; U11.27@132.912,47.97 U11.26@132.912,48.62 U11.25@132.912,49.27 ; U14.8@133.666,55.273 133.666,54.83 132.912,54.076 U11.19@132.912,53.17 U11.20@132.912,52.52 U11.21@132.912,51.87 U11.22@132.912,51.22 U11.23@132.912,50.57 U11.24@132.912,49.92 U11.25@132.912,49.27
  Bottom Layer w0.254: v1(94.733,56.832) 97.193,54.371 98.24,54.371 R137.2@98.325,54.286
  other v1: 126.451,50.394 127.96,50.394 129.257,50.394 131.15,50.57 131.474,51.419 132.548,53.857 133.519,53.882 100.838,55.191 100.838,55.941 100.838,56.691 93.424,57.639 94.782,59.149 132.293,59.89 94.481,64.984 92.469,66.497 92.469,67.507 89,67.53 90.986,67.54
  other v2: 111.981,54.861 111.981,55.912 111.981,56.963 111.981,58.014
TEMP_Bat_H1_init: R155.2 U7.49 | length 17.5
  Top Layer w0.254: v1(117.686,103.796) 118.082,104.192 122.542,104.192 122.595,104.244 124.666,104.244 129.264,108.842 129.362,108.842 131.111,110.59 R155.2@131.136,110.59
  Bottom Layer w0.254: U7.49@116.508,103.594 117.42,103.594 117.622,103.796 v1(117.686,103.796)
TEMP_Bat_H2_init: R158.2 U12.49 | length 15.6
  Top Layer w0.254: v1(114.666,54.404) 115.385,54.404 116.332,55.351 126.297,55.351 R158.2@127.975,53.673
  Bottom Layer w0.254: U12.49@113.462,54.389 113.47,54.396 114.659,54.396 v1(114.666,54.404)
TEMP_Bat_L1_init: R117.1 U10.49 | length 52.3
  Top Layer w0.254: v1(117.457,117.158) 117.458,117.156 118.614,117.156 118.987,117.529 122.383,117.529 124.385,119.532 124.385,121.685 129.481,126.781 129.481,137.645 133.908,142.071 v1(145.41,142.071) ; v1(149.445,141.555) 150.462,141.555 R117.1@150.557,141.65
  Layer 2 w0.254: v1(145.41,142.071) 148.929,142.071 v1(149.445,141.555)
  Bottom Layer w0.254: U10.49@116.424,117.146 116.43,117.152 117.451,117.152 v1(117.457,117.158)
TEMP_Bat_L2_init: R120.1 U15.49 | length 113.6
  Top Layer w0.254: v1(114.669,67.706) 114.718,67.754 115.044,67.754 116.153,68.863 116.153,68.908 116.338,69.094 121.755,69.094 124.874,72.213 131.408,72.213 132.141,71.48 132.141,68.516 134.941,65.717 141.083,65.717 158.987,83.621 158.987,120.781 v1(157.599,122.169) ; R120.1@156.908,137.122 156.953,137.077 v1(156.953,135.107)
  Layer 2 w0.254: v1@156.935,135.109 156.953,135.092 156.953,122.815 v1(157.599,122.169)
  Bottom Layer w0.254: U15.49@113.462,67.706 v1(114.669,67.706)
TEMP_Batt_H1_Buff: C142.2 J8.4 R51.1 | length 48.4
  Top Layer w0.254: v1(141.344,138.762) 141.336,138.754 141.336,130.279 148.969,122.646 148.969,117.336 147.999,116.366 C142.2@147.999,116.341 147.953,116.296 R51.1@146.534,116.296
  Layer 2 w0.254: v1(141.344,138.762) 141.344,146.063 141.539,146.258 141.556,146.258 150.446,155.148 150.446,155.392 J8.4@150.84,155.787
TEMP_Batt_H2_Buff: C152.2 J8.12 R159.1 | length 123.4
  Top Layer w0.254: R159.1@143.688,58.054 C152.2@145.466,58.054 ; C152.2@145.468,58.125 153.06,58.125 161.041,66.105 161.041,121.958 156.548,126.451 156.368,126.451 v1(151.827,130.992)
  Layer 2 w0.254: J8.12@145.94,156.201 140.805,151.066 140.805,138.549 148.363,130.992 v1(151.827,130.992)
TEMP_Batt_L1_Buff: J8.2 R116.2 | length 15.6
  Top Layer w0.254: R116.2@150.082,147.969 150.387,148.274 150.387,148.67 150.767,149.05 151.748,150.031 151.805,150.031 151.932,150.158 v1(152,150.158) ; J8.2@152.085,155.837 152.211,155.963 155.754,155.963 155.836,156.044 v1(156.516,156.044)
  Layer 2 w0.254: v1(152,150.158) 154.077,152.235 154.455,152.235 156.484,154.263 156.484,156.011 v1(156.516,156.044)
TEMP_Batt_L2_Buff: J8.10 R121.2 | length 11
  Top Layer w0.254: J8.10@146.905,155.896 151.504,151.297 154.068,151.297 R121.2@155.457,149.907
TEMP_Boost1_Buff: J8.8 R108.2 | length 21.8
  Top Layer w0.254: J8.8@148.175,155.896 148.261,155.896 151.319,152.839 155.189,152.839 156.607,151.421 156.607,145.816 158.891,143.533 R108.2@161.56,143.533
TEMP_Boost1_init: R109.1 U1.49 | length 82.2
  Top Layer w0.254: R109.1@161.859,132.78 161.94,132.699 v1(161.94,131.5) ; v1(170.772,109.232) 170.726,109.186 170.726,79.355 v1(175.944,74.137)
  Layer 2 w0.254: v1(161.94,131.5) 165.205,128.235 165.205,116.087 168.249,113.043 168.474,113.043 170.772,110.745 v1(170.772,109.232)
  Bottom Layer w0.254: v1(175.944,74.137) 178.301,71.78 U1.49@178.301,57.567
TEMP_Boost2_Buff: J8.6 R113.2 | length 27.5
  Top Layer w0.254: J8.6@149.416,156.011 150.368,155.059 150.415,155.059 152.231,153.243 158.61,153.243 160.311,151.542 166.523,151.542 167.377,150.688 167.377,146.03 167.268,145.921 167.268,143.881 R113.2@166.92,143.533
TEMP_Boost2_init: R112.1 U4.49 | length 118.2
  Top Layer w0.254: v1(166.598,128.269) R112.1@166.598,132.794 ; R112.1@166.665,132.848 R112.1@166.719,132.794 ; v1(173.468,111.699) 180.173,111.699 182.982,108.89 182.982,98.126 192.663,88.445 220.546,88.445 227.641,81.351 v1(227.641,74.348)
  Layer 2 w0.254: v1(166.598,128.269) 166.598,122.547 166.544,122.493 166.544,116.84 171.685,111.699 v1(173.468,111.699)
  Bottom Layer w0.254: U4.49@225.792,62.035 225.792,72.499 v1(227.641,74.348)
VS_Batt1+: J6.10 R152.2 TP32.1 | length 101.9
  Top Layer w0.254: R152.2@27.281,153.977 27.307,153.951 28.708,153.951 28.829,154.072 v1(28.898,154.072) 28.908,154.062 28.908,149.6 TP32.1@28.918,149.589
  Layer 2 w0.254: v1(28.898,154.072) 29.97,153 120.101,153 122.038,154.937 122.038,155.029 J6.10@122.905,155.896
VS_Batt1-: J6.12 R150.2 TP28.1 | length 105.4
  Top Layer w0.254: R150.2@27.233,161.785 27.283,161.735 v1(28.326,161.735) 28.342,161.751 30.864,161.751 TP28.1@30.88,161.766
  Layer 2 w0.254: v1(28.326,161.735) 28.326,155.852 30.774,153.404 119.934,153.404 121.634,155.104 121.634,155.895 J6.12@121.635,155.896
VS_Boost1+: J6.15 R87.2 TP31.1 | length 195.6
  Top Layer w0.254: R87.2@128.371,35.155 128.389,35.173 130.548,35.173 ; TP31.1@130.629,37.014 130.629,35.254 130.548,35.173 ; v1@164.966,108.681 164.974,108.681 165.649,108.007 165.649,54.8 168.594,51.855 168.594,46.715 167.973,46.094 158.85,46.094 149.859,37.103 138.251,37.103 136.321,35.173 130.548,35.173
  Bottom Layer w0.254: J6.15@119.095,157.166 119.095,160.713 121.027,162.645 132.62,162.645 134.741,160.524 134.741,138.871 v1(164.948,108.664)
VS_Boost1-: J6.17 R149.2 TP27.1 | length 210
  Top Layer w0.254: v1(122.215,25.986) 123.247,25.986 R149.2@123.311,26.05 ; v1(141.687,36.554) 149.942,36.554 159.06,45.672 168.182,45.672 169.11,46.6 169.11,52.048 166.156,55.003 v1(166.156,108.448)
  Layer 2 w0.254: v1(122.215,25.986) 122.263,26.035 122.263,27.68 129.752,35.169 133.128,35.169 133.848,35.889 134.173,35.889 134.182,35.879 135.56,35.879 ; TP27.1@136.033,37.435 135.958,37.435 135.56,37.036 135.56,35.879 ; v1(141.687,36.554) 141.618,36.554 141.245,36.182 140.981,36.182 140.679,35.879 135.56,35.879
  Bottom Layer w0.254: J6.17@117.825,157.166 117.825,160.015 120.859,163.049 132.801,163.049 135.145,160.706 135.145,139.218 165.866,108.496 166.107,108.496 v1(166.156,108.448)
VS_Boost2+: J6.11 R86.2 TP30.1 | length 194.5
  Top Layer w0.254: R86.2@122.561,34.695 122.311,34.945 122.311,35.675 123.438,36.802 ; TP30.1@123.218,38.593 123.438,38.373 123.438,36.802 ; v1(163.838,106.343) 163.838,100.805 163.665,100.631 163.665,55.641 167.626,51.68 167.626,47.592 167.478,47.443 158.756,47.443 149.923,38.611 129.341,38.611 127.532,36.802 123.438,36.802
  Bottom Layer w0.254: J6.11@121.635,157.665 121.635,159.054 124.242,161.661 130.722,161.661 133.083,159.301 133.083,136.793 163.491,106.385 163.796,106.385 v1(163.838,106.343)
VS_Boost2-: J6.13 R151.2 TP29.1 | length 213.8
  Top Layer w0.254: R151.2@121.092,27.144 120.799,27.437 120.799,27.138 121.153,27.138 121.314,26.977 v1@121.314,25.98 ; v1(143.929,37.868) 143.934,37.872 149.756,37.872 158.923,47.039 167.882,47.039 168.03,47.188 168.03,51.847 164.069,55.809 164.069,100.464 164.317,100.713 164.317,103.612 164.369,103.664 164.369,106.563 164.348,106.583 164.348,107.152 v1(164.3,107.201)
  Layer 2 w0.254: TP29.1@118.478,34.999 120.018,33.459 120.018,27.305 v1(121.343,25.98) 121.343,25.149 121.491,25 124.516,25 134.991,35.475 141.798,35.475 143.929,37.606 v1(143.929,37.868)
  Bottom Layer w0.254: J6.13@120.365,157.166 120.365,158.49 123.94,162.065 130.905,162.065 133.584,159.387 133.584,137.055 163.488,107.151 163.742,107.151 163.743,107.152 164.251,107.152 v1(164.3,107.201)
pads on no net: FID1.1 FID2.1 FID3.1 FID4.1 FID5.1 FID6.1 J1.2 J6.18 J6.19 J6.20 J6.21 J8.18 J8.20 J8.22 L1.3 L1.4 L1.7 L1.8 L1.9 L1.10 L1.11 L1.12 L4.3 L4.4 L4.7 L4.8 L4.9 L4.10 L4.11 L4.12 L9.2 L9.3 L9.4 L9.5 L9.7 L9.8 L9.9 L9.10 L9.11 L9.12 L13.2 L13.3 L13.4 L13.5 L13.7 L13.8 L13.9 L13.10 L13.11 L13.12 L18.7 L18.8 L18.9 L18.10 L18.11 L18.12 LBL1.0 MP1. MP1.1 MP2. MP2.1 MP3. MP3.1 MP4. MP4.1 MP5. MP5.1 MP6. MP6.1 MP7. MP7.1 MP8. MP8.1 MP9. MP9.1 U1.1 U1.16 U1.17 U1.27 U1.43 U1.47 U1.52 U4.1 U4.16 U4.17 U4.27 U4.43 U4.47 U4.52 U6.32 U7.1 U7.16 U7.17 U7.27 U7.43 U7.47 U7.52 U9.7 U9.10 U10.1 U10.16 U10.17 U10.27 U10.43 U10.47 U10.52 U11.32 U12.1 U12.16 U12.17 U12.27 U12.43 U12.47 U12.52 U14.7 U14.10 U15.1 U15.16 U15.17 U15.27 U15.43 U15.47 U15.52
copper on no net:
  other v1: 144.505,98.596

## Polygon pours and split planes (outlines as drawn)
DC_Bus- on Top Layer (solid, remove dead copper, pour order 192): 32 vertices, not listed, extent 15.916,70.635 121.454,121.427
"BAT Bus+" on Top Layer "TOP_LAYER_BAT_BUS+_P107" (solid, remove dead copper, pour order 107): 21 vertices, not listed, extent 4.993,92.39 37.396,121
NetC63_1 on Top Layer "TOP_LAYER_NETC63_1_P129" (solid, remove dead copper, pour order 129): 103.337,51.489 101.687,49.839 101.687,49.86 99.488,49.86 99.488,48.261 99.55,48.324 104.738,48.324 104.738,49.815 104.738,51.489
"PV2 Bus+" on Top Layer "TOP_LAYER_PV2_BUS+_P000" (solid, remove dead copper, pour order 0): 21 vertices, not listed, extent 29,1 241,28.05
GND_HVN on Top Layer "TOP_LAYER_GND_HVN_P189" (solid, remove dead copper, pour order 189): 126.329,139.982 125.529,139.182 123.492,139.182 122.806,139.868 122.806,142.131 123.38,142.706 125.64,142.706 126.329,142.018
12V_HVN on Top Layer "TOP_LAYER_12V_HVN_P188" (solid, remove dead copper, pour order 188): 125.824,145.097 125.45,144.723 123.385,144.723 122.7,145.408 122.7,147.646 124.017,148.963 124.818,148.963 125.824,147.956
12V_HVN on Top Layer "TOP_LAYER_12V_HVN_P187" (solid, remove dead copper, pour order 187): 116.355,135.428 117.026,136.099 117.094,136.099 117.832,136.099 119.192,134.74 119.192,133.158 117.938,131.904 116.355,131.904
SW1 on Top Layer "TOP_LAYER_SW1_P186" (solid, remove dead copper, pour order 186): 103.192,104.378 105.692,104.378 105.692,106.735 103.192,106.735
SW2 on Top Layer "TOP_LAYER_SW2_P185" (solid, remove dead copper, pour order 185): 100.588,54.77 102.803,54.77 102.803,57.499 100.588,57.499
DC_Bus+ on Top Layer "TOP_LAYER_DC_BUS+_P086" (solid, remove dead copper, pour order 86): 105.069,100.457 103.921,99.309 103.921,96.766 104.216,96.471 122.828,96.471 122.828,99.163 115.487,99.163 113.61,101.04 112.103,101.04 106.108,100.998 106.108,102.249 105.069,102.249
DC_Bus- on Top Layer "TOP_LAYER_DC_BUS-_P182" (solid, remove dead copper, pour order 182): 203.91,48.869 203.91,46.721 202.433,45.244 189.31,45.244 187.51,47.044 187.51,48.244 188.135,48.869
DC_Bus- on Top Layer "TOP_LAYER_DC_BUS-_P181" (solid, remove dead copper, pour order 181): 254.177,52.674 254.877,51.774 254.877,50.632 253.294,49.049 239.577,49.049 237.777,50.849 237.777,52.049 238.402,52.674
DC_Bus+ on Top Layer "TOP_LAYER_DC_BUS+_P180" (solid, remove dead copper, pour order 180): 230.008,66.673 230.008,64.643 230.395,64.256 234.836,64.256 237.07,62.022 237.07,56.265 238.712,54.623 254.164,54.623 255,55.459 255,70.717 252.294,73.424 236.758,73.424
DC_Bus+ on Top Layer "TOP_LAYER_DC_BUS+_P179" (solid, remove dead copper, pour order 179): 188.46,68.429 182.222,62.191 182.222,61.17 183.466,59.927 187.502,59.927 189.122,58.307 189.122,51.467 190.416,50.173 203.304,50.173 204.949,51.818 204.949,64.897 201.417,68.429
NetD3_2 on Top Layer "TOP_LAYER_NETD3_2_P178" (solid, remove dead copper, pour order 178): 229.901,60.523 229,59.991 229,40 231.216,38.016 237.984,38.016 237.984,41.697 237.984,47.016 234.458,49.649 234.458,59.502 233.485,60.557 233.462,60.535 230.115,60.535
NetD1_2 on Top Layer "Top Layer-NetD1_2" (solid, remove dead copper, pour order 177): 20 vertices, not listed, extent 181.579,37.987 195.003,56.767
Boost1_IN+ on Top Layer "TOP_LAYER_BOOST1_IN+_P175" (solid, remove dead copper, pour order 175): 23 vertices, not listed, extent 1.092,46 55.058,70
GND_HVN on Top Layer "TOP_LAYER_GND_HVN_P153" (solid, remove dead copper, pour order 153): 137.501,150.976 138.004,150.474 147.746,150.474 148.537,151.264 148.537,153.118 147.664,153.991 138.521,153.991 137.501,152.971
DC_Bus- on Top Layer "TOP_LAYER_DC_BUS-_P168" (solid, remove dead copper, pour order 168): 177.321,107.889 177.4,107.811 179.977,107.811 180.254,107.534 180.254,103.367 178.711,103.367 177.355,104.722 177.355,107.811
DC_Bus- on Top Layer "TOP_LAYER_DC_BUS-_P167" (solid, remove dead copper, pour order 167): 115.394,129.198 116.194,129.998 118.23,129.998 118.916,129.311 118.916,127.048 118.342,126.474 116.082,126.474 115.394,127.162
DC_Bus- on Top Layer "TOP_LAYER_DC_BUS-_P151" (solid, remove dead copper, pour order 151): 157.681,147.319 157.724,147.277 167.044,147.277 167.645,146.675 167.645,145.303 167.614,145.303 167.225,144.914 158.101,144.914 158.101,144.94 157.371,145.669 157.371,146.569
Boost1_IN+ on Top Layer "TOP_LAYER_BOOST1_IN+_P112" (solid, remove dead copper, pour order 112): 30.975,55.013 31.044,55.013 32.084,56.053 52,56.053 52,56.046 52.975,55.071 52.975,48.975 52,48 31.975,48 30.975,49
NetJ1_1 on Top Layer "TOP_LAYER_NETJ1_1_P058" (solid, remove dead copper, pour order 58): 191.709,105.939 193.17,104.478 193.17,101.28 196.403,98.048 206.252,98.048 207.435,96.864 207.435,91 194.829,91 186.492,99.337 186.492,104.648 187.782,105.939
"PV1 Bus+" on Top Layer "TOP_LAYER_PV1_BUS+_P088" (solid, remove dead copper, pour order 88): 138.722,34.315 138.722,31.029 149.136,31.029 150,31.893 150,33.859 149.544,34.315
DC_Bus- on Top Layer "TOP_LAYER_DC_BUS-_P165" (solid, remove dead copper, pour order 165): 149.216,54.309 150.16,53.382 150.16,49.585 148.41,47.835 148.41,46.585 142.91,46.585 142.91,53.542 142.728,53.724 140.089,53.724 138.498,55.315 138.548,55.365 140.107,55.365 141.188,54.283 141.214,54.309
SW1 on Top Layer "TOP_LAYER_SW1_P121" (solid, remove dead copper, pour order 121): 137.142,112.88 137.142,112.768 137.4,112.524 137.4,106.122 136.9,105.622 135.4,105.622 135.4,106.122 128.846,106.122 128.846,107.165 129.806,108.126 133.651,108.126 135.032,109.507 135.032,111.408 135.73,112.106 135.73,112.88
DC_Bus- on Top Layer "TOP_LAYER_DC_BUS-_P164" (solid, remove dead copper, pour order 164): 141.041,112.92 140.992,112.872 140.992,112.485 141.452,112.025 145.252,112.025 145.52,111.756 145.52,104.617 150.809,104.617 150.809,105.862 152.457,107.51 152.457,111.219 151.168,112.485 144.503,112.485 144.068,112.92
GND_HVN on Top Layer "TOP_LAYER_GND_HVN_P154" (solid, remove dead copper, pour order 154): 156.53,148.884 157.032,148.381 166.775,148.381 167.144,148.75 167.144,150.171 166.382,150.933 157.2,150.933 156.53,150.263
DC_Bus- on Top Layer "TOP_LAYER_DC_BUS-_P152" (solid, remove dead copper, pour order 152): 137.668,148.461 138.17,148.963 147.763,148.963 148.356,148.37 148.356,146.483 147.907,146.035 138.073,146.035 137.657,146.451 137.657,148.525
NetR69_2 on Top Layer "TOP_LAYER_NETR69_2_P136" (solid, remove dead copper, pour order 136): 31.984,157.457 31.984,154.432 32.213,154.203 33.875,154.203 33.875,155.078 33.911,155.114 32.871,156.154 32.871,157.457
NetR68_2 on Top Layer "TOP_LAYER_NETR68_2_P135" (solid, remove dead copper, pour order 135): 32.125,151.97 32.125,149.205 33.875,149.205 33.875,151.97
NetR44_2 on Top Layer "TOP_LAYER_NETR44_2_P134" (solid, remove dead copper, pour order 134): 21.742,151.741 21.767,151.716 21.767,150.403 21.966,150.204 21.966,148.167 22.993,148.167 23.492,148.666 23.492,150.958 23.492,151.741
NetR43_2 on Top Layer "TOP_LAYER_NETR43_2_P133" (solid, remove dead copper, pour order 133): 16.376,150.242 16.136,150.002 16.136,149.042 18.211,149.042 18.938,148.316 18.938,148.167 19.98,148.167 19.98,150.242
DC_Bus- on Top Layer "TOP_LAYER_DC_BUS-_P029" (solid, remove dead copper, pour order 29): 99.488,41.258 99.488,44.488 100.123,45.123 107.648,45.123 118.037,45.123 121.491,45.123 121.491,41.258
DC_Bus+ on Top Layer "TOP_LAYER_DC_BUS+_P028" (solid, remove dead copper, pour order 28): 108.865,51.377 108.865,50.638 109.081,50.422 121.272,50.509 121.272,47.268 106.113,47.268 106.111,50.115 106.111,51.377
DC_Bus+ on Top Layer "TOP_LAYER_DC_BUS+_P056" (solid, remove dead copper, pour order 56): 219.087,107.258 225.923,107.258 227.981,105.2 227.981,93.092 225.463,90.575 213.968,90.575 211.876,92.666 211.876,100.047 214.62,102.791
SW2 on Top Layer "TOP_LAYER_SW2_P124" (solid, remove dead copper, pour order 124): 133.798,45.16 131.262,45.16 131.262,46.36 131.862,46.36 131.962,46.26 133.798,46.26
SW2 on Top Layer "TOP_LAYER_SW2_P123" (solid, remove dead copper, pour order 123): 19 vertices, not listed, extent 125.244,48.371 134.356,55.516
SW1 on Top Layer "TOP_LAYER_SW1_P122" (solid, remove dead copper, pour order 122): 137.385,103.062 134.885,103.062 134.885,104.262 135.485,104.262 135.585,104.162 137.385,104.162
Boost2_IN+ on Top Layer "TOP_LAYER_BOOST2_IN+_P111" (solid, remove dead copper, pour order 111): 22 vertices, not listed, extent 0.571,19.5 52,40.987
"BAT Bus-" on Top Layer "TOP_LAYER_BAT_BUS-_P116" (solid, remove dead copper, pour order 116): 31.979,146.989 31.979,145.185 31.968,145.174 33.968,145.174 33.968,146.875 33.854,146.989
"BAT Bus+" on Top Layer "TOP_LAYER_BAT_BUS+_P115" (solid, remove dead copper, pour order 115): 16.011,146.815 16.011,145.011 16,145 18,145 18,146.701 17.886,146.815
"PV1 Bus+" on Top Layer "TOP_LAYER_PV1_BUS+_P113" (solid, remove dead copper, pour order 113): 31.278,36.688 31.347,36.688 32.387,37.727 52.303,37.727 52.303,37.72 53.278,36.745 53.278,30.649 52.303,29.674 32.278,29.674 31.278,30.674
NetR30_2 on Top Layer "TOP_LAYER_NETR30_2_P092" (solid, remove dead copper, pour order 92): 111.891,30.479 113.641,30.479 113.641,31.404 114.167,31.93 114.167,33.68 113.277,33.68 111.891,32.294 111.891,31.37
NetR28_2 on Top Layer "TOP_LAYER_NETR28_2_P091" (solid, remove dead copper, pour order 91): 111.891,28.247 111.891,25.952 111.818,25.879 113.568,25.879 113.568,28.174 113.641,28.247
NetR36_2 on Top Layer "TOP_LAYER_NETR36_2_P090" (solid, remove dead copper, pour order 90): 131.273,29.35 131.273,27.6 133.896,27.6 134.65,28.354 134.65,29.35
NetR33_2 on Top Layer "TOP_LAYER_NETR33_2_P089" (solid, remove dead copper, pour order 89): 135.891,33.216 135.891,31.455 132.9,31.455 132.9,32.692 133.464,33.216
NetC66_1 on Top Layer "TOP_LAYER_NETC66_1_P087" (solid, remove dead copper, pour order 87): 96.577,102.27 96.577,100.916 96.77,100.723 103.988,100.723 103.988,102.311
DC_Bus- on Layer 1 "Layer 1-GND_BAT" (solid, remove dead copper, pour order 143): 60 vertices, not listed, extent 111.243,39.569 165.282,149.657
GND_HVN on Layer 1 "Layer 1-GND_HVN" (solid, remove dead copper, pour order 161): 52 vertices, not listed, extent 7.462,56.427 169.673,165
DC_Bus- on Layer 1 "Layer 1-DC_Bus-" (solid, remove dead copper, pour order 139): 48 vertices, not listed, extent 155.959,54.503 228.557,147.244
GND_HVN on Layer 1 "LAYER_1_GND_HVN_P149" (solid, remove dead copper, pour order 149): 33 vertices, not listed, extent 114.988,24.25 170.11,111.005
GND_HVN on Layer 1 "LAYER_1_GND_HVN_P148" (solid, remove dead copper, pour order 148): 23 vertices, not listed, extent 172.462,20 216.345,104.492
NetC2_2 on Layer 1 "LAYER_1_NETC2_2_P109" (solid, remove dead copper, pour order 109): 19 vertices, not listed, extent 18,94.007 48.504,121
DC_Bus- on Layer 1 "LAYER_1_DC_BUS-_P183" (solid, pour order 183): 20 vertices, not listed, extent 15.916,70.635 73.622,121.5
DC_Bus- on Layer 1 "LAYER_1_DC_BUS-_P044" (solid, remove dead copper, pour order 44): 203.91,48.179 203.91,46.721 202.433,45.244 189.31,45.244 187.866,46.688 187.866,47.703 188.341,48.179
DC_Bus- on Layer 1 "LAYER_1_DC_BUS-_P043" (solid, remove dead copper, pour order 43): 254.498,52.261 254.877,51.774 254.877,50.632 253.294,49.049 239.577,49.049 237.777,50.849 237.777,52.049 237.988,52.261
DC_Bus+ on Layer 1 "LAYER_1_DC_BUS+_P051" (solid, remove dead copper, pour order 51): 230.008,66.673 230.008,64.643 230.395,64.256 234.836,64.256 237.07,62.022 237.07,56.265 238.437,54.899 254.44,54.899 255,55.459 255,70.717 252.294,73.424 236.758,73.424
